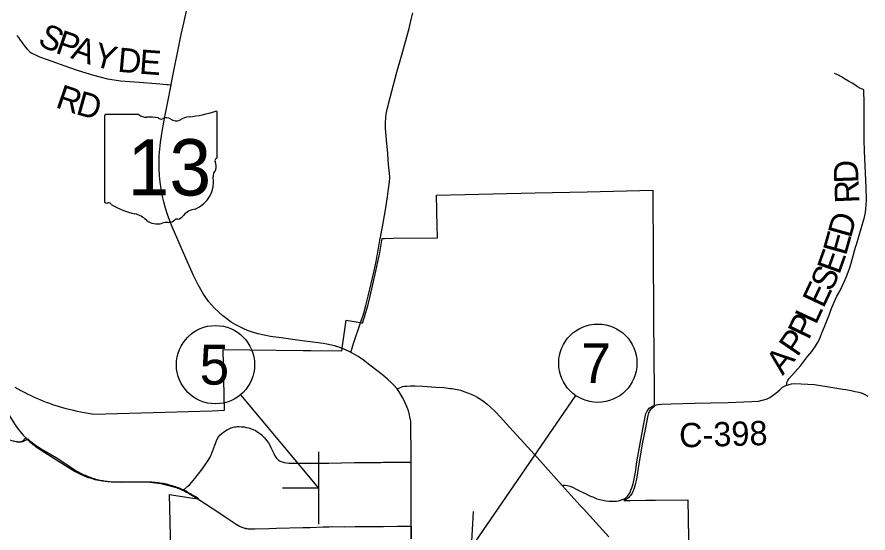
# Model space of a CAD drawing. Extents: x 40529 to 41139, y 15164 to 15584.
# Drawn here: x 40677.8 to 40737.7, y 15391.5 to 15427.7 of the extents above; entities that cross this region are included whole.
import ezdxf

# ---------------------------------------------------------------- set-up
doc = ezdxf.new("R2010")
doc.units = 0
for name, color, linetype in [('Default', 7, 'Continuous'), ('GM_X_Corporation', 7, 'Continuous'), ('GM_X_County_Road', 7, 'Continuous'), ('GM_X_County_Road_Text', 7, 'Continuous'), ('GM_X_State_Location', 7, 'Continuous'), ('GM_X_State_Route', 7, 'Continuous'), ('GM_X_State_Shield', 7, 'Continuous'), ('GM_X_Township_Road', 7, 'Continuous'), ('GM_X_Township_Road_Text', 7, 'Continuous'), ('SH_Data', 7, 'Continuous'), ('SH_Text', 7, 'Continuous')]:
    doc.layers.add(name, color=color, linetype=linetype)

msp = doc.modelspace()

# ---------------------------------------------------------------- linework, layer by layer
at = {"layer": 'Default'}
for p, q in [((40699.053, 15392.086), (40699.048, 15397.182)), ((40699.05, 15394.634), (40696.502, 15394.631)), ((40709.776, 15390.449), (40709.922, 15392.993))]:
    msp.add_line(p, q, dxfattribs=at)
at = {"layer": 'GM_X_Corporation'}
for points in [[(40677.684, 15401.723), (40677.895, 15401.602), (40678.108, 15401.484), (40678.322, 15401.37), (40678.539, 15401.259), (40678.758, 15401.152), (40678.978, 15401.049), (40679.2, 15400.949), (40679.423, 15400.853), (40679.649, 15400.761), (40679.875, 15400.673), (40680.103, 15400.589), (40680.333, 15400.508), (40680.564, 15400.431), (40680.796, 15400.359), (40681.029, 15400.29), (40681.264, 15400.225), (40681.499, 15400.164), (40681.795, 15400.093), (40682.051, 15400.036), (40682.309, 15399.982), (40682.568, 15399.933), (40682.827, 15399.888), (40683.228, 15399.826), (40691.537, 15400.05), (40692.408, 15400.114), (40692.321, 15404.358), (40697.953, 15404.3), (40698.487, 15404.294), (40700.671, 15404.272), (40700.718, 15404.618), (40700.963, 15406.416), (40701.954, 15406.248), (40702.106, 15406.205), (40702.331, 15406.898), (40702.484, 15407.435), (40702.654, 15408.1), (40703.064, 15409.868), (40703.202, 15410.515), (40703.286, 15410.945), (40703.304, 15411.046), (40703.501, 15412.166), (40703.666, 15412.167), (40704.274, 15412.173), (40707.388, 15412.201), (40707.352, 15413.986), (40707.348, 15414.156), (40707.327, 15415.212), (40714.26, 15415.365), (40717.919, 15415.446), (40722.534, 15415.548), (40722.561, 15410.772), (40722.582, 15407.158), (40722.605, 15403.275), (40722.612, 15402.043), (40722.62, 15400.712), (40722.62, 15400.589), (40722.621, 15400.532), (40722.625, 15400.336), (40722.491, 15400.261), (40722.422, 15400.208), (40722.365, 15400.146), (40722.318, 15400.074), (40722.278, 15399.996), (40722.232, 15399.913), (40722.197, 15399.827), (40722.169, 15399.72), (40721.978, 15398.741), (40721.785, 15397.737), (40721.564, 15396.449), (40721.481, 15395.898), (40721.46, 15395.712), (40721.374, 15395.255), (40721.291, 15394.893), (40721.206, 15394.624), (40721.138, 15394.448), (40721.074, 15394.283), (40721.012, 15394.189), (40720.96, 15394.116), (40720.897, 15394.041), (40720.832, 15393.968), (40720.756, 15393.899), (40720.673, 15393.85), (40720.586, 15393.809), (40720.477, 15393.768), (40720.481, 15393.764), (40720.859, 15393.768), (40720.935, 15393.769), (40722.015, 15393.78), (40722.721, 15393.787), (40724.997, 15393.81), (40725.116, 15385.709)], [(40688.711, 15387.419), (40688.541, 15394.18), (40690.184, 15393.933), (40690.608, 15393.869), (40690.516, 15393.928), (40690.392, 15394.007), (40690.257, 15394.088), (40690.101, 15394.177), (40690.027, 15394.216), (40689.85, 15394.309), (40689.712, 15394.421), (40689.61, 15394.469), (40689.506, 15394.515), (40689.401, 15394.559), (40689.296, 15394.602), (40689.19, 15394.642), (40689.083, 15394.681), (40688.976, 15394.718), (40688.868, 15394.753), (40688.76, 15394.786), (40688.651, 15394.817), (40688.541, 15394.847), (40688.431, 15394.874), (40688.32, 15394.9), (40688.209, 15394.923), (40688.098, 15394.945), (40687.986, 15394.964), (40687.874, 15394.982), (40687.762, 15394.998), (40687.649, 15395.011), (40687.536, 15395.023), (40687.514, 15395.025), (40687.423, 15395.033), (40687.31, 15395.041), (40687.196, 15395.047), (40687.083, 15395.051), (40686.862, 15395.053), (40684.948, 15395.037), (40684.849, 15395.037), (40684.749, 15395.038), (40684.65, 15395.042), (40684.551, 15395.047), (40684.452, 15395.054), (40684.353, 15395.063), (40684.254, 15395.073), (40684.156, 15395.085), (40684.058, 15395.099), (40683.96, 15395.115), (40683.862, 15395.132), (40683.764, 15395.151), (40683.667, 15395.172), (40683.571, 15395.194), (40683.474, 15395.218), (40683.379, 15395.244), (40683.283, 15395.271), (40683.188, 15395.3), (40683.094, 15395.331), (40683, 15395.363), (40682.907, 15395.397), (40682.814, 15395.433), (40682.722, 15395.47), (40682.631, 15395.509), (40682.54, 15395.549), (40682.45, 15395.591), (40682.361, 15395.635), (40682.273, 15395.68), (40682.185, 15395.727), (40682.098, 15395.775), (40682.012, 15395.824), (40681.927, 15395.876), (40681.828, 15395.938), (40680.569, 15396.75), (40679.526, 15397.354), (40679.268, 15397.526), (40679.019, 15397.711), (40678.78, 15397.909), (40678.602, 15398.077), (40678.448, 15397.986), (40678.412, 15397.965), (40678.361, 15397.939), (40678.308, 15397.917), (40678.278, 15397.905), (40678.223, 15397.888), (40678.192, 15397.88), (40678.161, 15397.874), (40678.104, 15397.865), (40678.046, 15397.861), (40677.988, 15397.86), (40677.931, 15397.864), (40677.873, 15397.872), (40677.842, 15397.878), (40677.786, 15397.892)]]:
    msp.add_lwpolyline(points, dxfattribs=at)
at = {"layer": 'GM_X_County_Road'}
for points in [[(40703.373, 15412.203), (40703.381, 15412.248), (40703.514, 15412.979), (40703.726, 15414.172), (40703.874, 15415.085), (40703.954, 15415.64), (40704.012, 15416.116), (40704.027, 15416.451), (40704.007, 15416.758), (40703.977, 15417.131), (40703.928, 15417.685), (40703.889, 15418.134), (40703.795, 15419.079), (40703.777, 15419.37), (40703.74, 15419.874), (40703.726, 15420.339), (40703.756, 15420.62), (40703.78, 15420.891), (40703.854, 15421.247), (40703.913, 15421.474), (40703.948, 15421.621), (40704.54, 15423.846), (40704.831, 15424.892), (40705.392, 15426.905), (40705.541, 15427.541), (40705.66, 15428)], [(40701.974, 15406.226), (40701.997, 15406.297), (40702.199, 15406.918), (40702.352, 15407.454), (40702.522, 15408.119), (40702.932, 15409.886), (40703.07, 15410.532), (40703.154, 15410.961), (40703.172, 15411.062), (40703.369, 15412.181), (40703.373, 15412.203)], [(40701.307, 15404.163), (40701.421, 15404.558), (40701.49, 15404.793), (40701.974, 15406.226)], [(40722.473, 15400.363), (40722.498, 15400.376), (40722.64, 15400.432), (40722.795, 15400.477), (40722.893, 15400.493), (40723.169, 15400.516), (40723.817, 15400.55), (40725.492, 15400.593), (40726.607, 15400.609), (40727.813, 15400.641), (40728.929, 15400.683), (40729.487, 15400.701), (40729.951, 15400.745), (40730.212, 15400.794), (40730.321, 15400.819), (40730.558, 15400.903), (40730.755, 15401.002), (40730.923, 15401.1), (40731.174, 15401.298), (40731.451, 15401.534), (40731.653, 15401.712), (40731.747, 15401.766), (40731.84, 15401.815), (40731.933, 15401.853)], [(40731.933, 15401.853), (40731.974, 15401.87), (40732.116, 15401.909), (40732.284, 15401.944), (40732.51, 15401.965), (40732.955, 15401.954), (40733.429, 15401.929), (40733.89, 15401.905), (40734.165, 15401.87), (40734.891, 15401.746), (40735.893, 15401.578), (40736.088, 15401.544), (40736.463, 15401.475), (40736.754, 15401.421), (40737.01, 15401.362), (40737.237, 15401.288), (40737.425, 15401.209), (40737.651, 15401.084)], [(40720.354, 15393.812), (40720.436, 15393.842), (40720.522, 15393.884), (40720.605, 15393.932), (40720.681, 15394.001), (40720.747, 15394.074), (40720.809, 15394.15), (40720.861, 15394.222), (40720.923, 15394.316), (40720.988, 15394.481), (40721.055, 15394.656), (40721.14, 15394.925), (40721.223, 15395.287), (40721.309, 15395.744), (40721.33, 15395.929), (40721.413, 15396.48), (40721.633, 15397.767), (40721.826, 15398.769), (40722.018, 15399.747), (40722.045, 15399.854), (40722.08, 15399.941), (40722.126, 15400.023), (40722.166, 15400.101), (40722.213, 15400.173), (40722.27, 15400.235), (40722.339, 15400.288), (40722.473, 15400.363)], [(40676.892, 15398.131), (40677.118, 15398.073), (40677.657, 15397.919), (40677.836, 15397.887), (40677.926, 15397.88), (40678.016, 15397.882), (40678.104, 15397.895), (40678.19, 15397.921), (40678.261, 15397.967), (40678.309, 15398.015), (40678.446, 15398.152)], [(40716.154, 15394.821), (40716.225, 15394.832), (40716.294, 15394.842), (40716.366, 15394.845), (40716.494, 15394.821), (40716.681, 15394.762), (40716.874, 15394.687), (40717.194, 15394.53), (40717.857, 15394.215), (40718.202, 15394.046), (40718.303, 15394.005)], [(40718.303, 15394.005), (40718.591, 15393.887), (40719.019, 15393.772), (40719.23, 15393.737), (40719.453, 15393.708), (40719.769, 15393.701), (40719.97, 15393.715), (40720.113, 15393.744), (40720.327, 15393.802), (40720.354, 15393.812)]]:
    msp.add_lwpolyline(points, dxfattribs=at)
at = {"layer": 'GM_X_State_Route'}
for p, q in [((40690.468, 15393.917), (40692.237, 15392.767)), ((40705.542, 15391.073), (40705.543, 15391.959))]:
    msp.add_line(p, q, dxfattribs=at)
for points in [[(40700.259, 15404.581), (40700.232, 15404.588), (40699.932, 15404.661), (40699.597, 15404.731), (40699.354, 15404.773), (40698.8, 15404.859), (40697.875, 15404.979), (40696.396, 15405.171), (40695.659, 15405.28), (40695.202, 15405.365), (40694.749, 15405.471), (40694.392, 15405.574), (40694.042, 15405.697), (40693.785, 15405.805), (40693.534, 15405.924), (40693.206, 15406.099), (40692.89, 15406.294), (40692.585, 15406.506), (40692.293, 15406.735), (40692.012, 15406.978), (40691.745, 15407.236), (40691.491, 15407.508), (40691.313, 15407.721), (40691.145, 15407.943), (40690.935, 15408.25), (40690.742, 15408.567), (40690.564, 15408.894), (40690.236, 15409.563), (40689.851, 15410.411), (40688.737, 15412.977), (40688.562, 15413.408), (40688.403, 15413.845), (40688.263, 15414.289), (40688.142, 15414.737), (40688.039, 15415.191), (40687.959, 15415.649), (40687.897, 15416.11), (40687.853, 15416.573), (40687.826, 15417.038), (40687.818, 15417.503), (40687.83, 15417.968), (40687.862, 15418.432), (40687.914, 15418.894), (40688.01, 15419.539), (40688.171, 15420.457), (40688.407, 15421.645), (40688.659, 15422.94), (40688.692, 15423.11), (40689.372, 15426.494), (40689.572, 15427.404), (40689.753, 15428.127)], [(40701.307, 15404.163), (40701.235, 15404.197), (40700.979, 15404.312), (40700.776, 15404.4), (40700.569, 15404.479), (40700.312, 15404.568), (40700.259, 15404.581)], [(40704.555, 15401.579), (40704.525, 15401.619), (40704.343, 15401.833), (40704.146, 15402.033), (40703.872, 15402.286), (40703.515, 15402.587), (40702.634, 15403.273), (40702.186, 15403.607), (40701.803, 15403.873), (40701.483, 15404.067), (40701.307, 15404.163)], [(40704.555, 15401.579), (40704.625, 15401.617), (40704.722, 15401.669), (40704.829, 15401.717), (40704.936, 15401.759), (40705.064, 15401.783), (40705.223, 15401.796), (40705.489, 15401.81), (40705.792, 15401.81), (40706.355, 15401.79), (40707.271, 15401.727), (40707.837, 15401.689), (40708.303, 15401.634), (40708.409, 15401.616), (40708.766, 15401.555), (40709.011, 15401.496), (40709.318, 15401.399), (40709.574, 15401.303), (40709.923, 15401.151), (40710.178, 15401.016), (40710.416, 15400.868), (40710.648, 15400.705), (40710.876, 15400.529), (40711.1, 15400.343), (40711.435, 15400.018), (40711.811, 15399.621), (40712.437, 15398.934), (40713.99, 15397.215), (40716.154, 15394.821), (40717.425, 15393.415), (40717.65, 15393.167), (40719.427, 15391.208)], [(40705.484, 15399.439), (40705.475, 15399.504), (40705.42, 15399.783), (40705.347, 15400.053), (40705.212, 15400.405), (40705.101, 15400.659), (40704.982, 15400.913), (40704.845, 15401.159), (40704.693, 15401.394), (40704.555, 15401.579)], [(40677.306, 15399.697), (40677.447, 15399.461), (40677.701, 15399.071), (40677.917, 15398.769), (40678.148, 15398.478), (40678.332, 15398.269), (40678.446, 15398.152)], [(40705.527, 15397.478), (40705.523, 15398.53), (40705.52, 15398.851), (40705.507, 15399.128), (40705.502, 15399.31), (40705.484, 15399.439)], [(40678.446, 15398.152), (40678.526, 15398.069), (40678.73, 15397.881), (40678.946, 15397.706), (40679.247, 15397.488), (40679.793, 15397.133), (40681.606, 15395.987), (40681.926, 15395.798), (40682.255, 15395.625), (40682.508, 15395.51), (40682.767, 15395.407), (40683.031, 15395.318), (40683.298, 15395.241), (40683.569, 15395.179), (40683.844, 15395.132), (40684.212, 15395.089), (40684.676, 15395.06), (40685.141, 15395.049), (40686.54, 15395.073), (40686.914, 15395.067), (40687.195, 15395.05), (40687.567, 15395.008), (40687.936, 15394.947), (40688.302, 15394.87), (40688.665, 15394.777), (40689.023, 15394.665), (40689.374, 15394.534), (40689.462, 15394.493)], [(40705.528, 15396.44), (40705.529, 15396.667), (40705.527, 15397.478)], [(40705.543, 15391.959), (40705.543, 15392.301), (40705.534, 15393.599), (40705.526, 15395.737), (40705.528, 15396.44)], [(40689.462, 15394.493), (40689.491, 15394.48), (40689.63, 15394.417), (40689.877, 15394.283), (40690.355, 15393.99), (40690.468, 15393.917)], [(40692.237, 15392.767), (40692.464, 15392.62), (40693.238, 15392.103), (40693.476, 15391.963), (40693.642, 15391.884), (40693.699, 15391.864)], [(40693.699, 15391.864), (40693.813, 15391.823), (40693.899, 15391.801), (40694.074, 15391.776), (40694.255, 15391.766), (40694.537, 15391.762), (40695.521, 15391.797), (40696.066, 15391.807), (40697.921, 15391.856), (40698.429, 15391.871), (40699.361, 15391.906), (40699.571, 15391.912)], [(40699.571, 15391.912), (40699.781, 15391.919), (40699.92, 15391.923), (40700.851, 15391.919), (40701.608, 15391.924), (40702.229, 15391.929), (40703.453, 15391.943), (40703.589, 15391.944), (40704.581, 15391.951), (40705.015, 15391.955), (40705.413, 15391.958), (40705.543, 15391.959)]]:
    msp.add_lwpolyline(points, dxfattribs=at)
at = {"layer": 'GM_X_State_Shield'}
for p, q in [((40683.987, 15420.758), (40683.987, 15414.755)), ((40686.381, 15420.862), (40684.065, 15420.862)), ((40691.897, 15417.87), (40691.897, 15421.01)), ((40691.896, 15417.871), (40691.897, 15417.87))]:
    msp.add_line(p, q, dxfattribs=at)
for centre, radius, start, end in [((40684.077, 15420.771), 0.0916, 98.1301, 188.1301), ((40686.933, 15421.559), 0.889, 231.61951, 271.11188), ((40687.227, 15417.491), 3.191, 80.48669, 94.98827), ((40687.952, 15420.802), 0.256, 219.79206, 297.10237), ((40688.328, 15420.108), 0.533, 54.46668, 119.14113), ((40690.149, 15419.028), 1.688, 97.34618, 120.76885), ((40689.079, 15429.047), 8.388, 275.84447, 288.90645), ((40691.809, 15421.024), 0.0881, 351.86209, 97.738), ((40689.016, 15421.06), 0.641, 233.85621, 294.82819), ((40691.876, 15417.639), 0.136, 107.94398, 210.33697), ((40691.009, 15417.242), 0.818, 340.03296, 23.64957), ((40691.803, 15417.858), 0.0942, 289.60381, 7.73413), ((40692.212, 15416.556), 0.595, 136.8065, 186.92959), ((40689.549, 15416.156), 2.098, 292.30889, 8.98584), ((40684.078, 15414.742), 0.0925, 171.95839, 258.30661), ((40684.092, 15415.356), 0.706, 267.33899, 280.60386), ((40684.237, 15414.408), 0.254, 29.74838, 93.27175), ((40687.448, 15419.802), 6.058, 240.41292, 257.1985), ((40690.434, 15413.069), 1.149, 94.40312, 142.57675), ((40685.642, 15412.058), 1.895, 47.18416, 75.83597), ((40687.692, 15414.379), 1.203, 230.70037, 286.29184), ((40688.475, 15413.929), 0.641, 268.77702, 315.54927), ((40689.055, 15413.348), 0.18, 65.75173, 132.64842), ((40688.978, 15414.173), 0.678, 282.87319, 323.27711), ((40688.387, 15412.303), 0.988, 85.69512, 111.20995)]:
    msp.add_arc(centre, radius, start, end, dxfattribs=at)
at = {"layer": 'GM_X_Township_Road'}
msp.add_line((40704.54, 15396.447), (40705.528, 15396.44), dxfattribs=at)
for points in [[(40677.817, 15426.421), (40677.93, 15426.263), (40678.058, 15426.081), (40678.162, 15425.948), (40678.266, 15425.805), (40678.394, 15425.622), (40678.542, 15425.45), (40678.729, 15425.267), (40678.833, 15425.199), (40678.911, 15425.15), (40679.075, 15425.068), (40679.418, 15424.927), (40679.943, 15424.739), (40681.523, 15424.178), (40682.135, 15423.956), (40682.665, 15423.782), (40683.198, 15423.619), (40683.647, 15423.5), (40684.19, 15423.38), (40684.647, 15423.298), (40685.107, 15423.237), (40685.756, 15423.174), (40686.406, 15423.126), (40687.612, 15423.047), (40688.353, 15422.976), (40688.446, 15422.965), (40688.659, 15422.94)], [(40737.368, 15422.592), (40737.312, 15422.614), (40737.263, 15422.634), (40737.198, 15422.663), (40737.085, 15422.721), (40736.926, 15422.814), (40736.725, 15422.946), (40736.543, 15423.062), (40736.274, 15423.209), (40735.999, 15423.374), (40735.801, 15423.503), (40735.575, 15423.632), (40735.422, 15423.698), (40735.299, 15423.736)], [(40731.933, 15401.853), (40731.944, 15401.959), (40731.954, 15402.057), (40732.023, 15402.185), (40732.09, 15402.301), (40732.911, 15403.207), (40733.389, 15403.873), (40733.7, 15404.233), (40733.969, 15404.593), (40734.11, 15404.827), (40734.233, 15405.096), (40734.391, 15405.456), (40734.613, 15406.026), (40734.941, 15406.853), (40735.041, 15407.125), (40735.124, 15407.35), (40735.266, 15407.694), (40735.469, 15408.109), (40735.69, 15408.514), (40735.969, 15409.107), (40736.137, 15409.501), (40736.329, 15409.97), (40736.474, 15410.418), (40736.784, 15411.543), (40736.841, 15411.74), (40737.173, 15412.871), (40737.242, 15413.088), (40737.296, 15413.26), (40737.38, 15413.566), (40737.473, 15413.977), (40737.51, 15414.251), (40737.531, 15414.526), (40737.537, 15414.895), (40737.526, 15415.73), (40737.486, 15416.753), (40737.413, 15418.323), (40737.387, 15419.063), (40737.385, 15419.616), (40737.388, 15420.075), (40737.385, 15420.438), (40737.38, 15421.637), (40737.368, 15422.592)], [(40689.491, 15394.48), (40689.621, 15394.59), (40689.829, 15394.766), (40689.97, 15394.891), (40690.099, 15395.027), (40690.339, 15395.313), (40690.845, 15395.961), (40691.066, 15396.258), (40691.273, 15396.57), (40691.415, 15396.808), (40691.452, 15396.89), (40691.723, 15397.634), (40691.846, 15397.94), (40691.94, 15398.157), (40692.083, 15398.339), (40692.221, 15398.467), (40692.339, 15398.556), (40692.477, 15398.655), (40692.568, 15398.71)], [(40692.568, 15398.71), (40692.591, 15398.724), (40692.739, 15398.798), (40692.892, 15398.862), (40693.03, 15398.911), (40693.148, 15398.931), (40693.242, 15398.941), (40693.331, 15398.946), (40693.424, 15398.946), (40693.607, 15398.941), (40693.789, 15398.926), (40693.947, 15398.897), (40694.12, 15398.852), (40694.308, 15398.793), (40694.584, 15398.675), (40694.83, 15398.518), (40694.976, 15398.408), (40695.029, 15398.36)], [(40695.029, 15398.36), (40695.044, 15398.346), (40695.229, 15398.156), (40695.4, 15397.949), (40695.504, 15397.8), (40695.598, 15397.643), (40695.682, 15397.48), (40695.871, 15397.056), (40695.96, 15396.889), (40696.013, 15396.81), (40696.073, 15396.735), (40696.14, 15396.666), (40696.212, 15396.603), (40696.29, 15396.547), (40696.374, 15396.499), (40696.468, 15396.464), (40696.537, 15396.44), (40696.607, 15396.424), (40696.778, 15396.398), (40696.945, 15396.389), (40697.682, 15396.39), (40699.745, 15396.391)], [(40699.745, 15396.391), (40700.637, 15396.405), (40701.562, 15396.42)], [(40701.562, 15396.42), (40703.393, 15396.439), (40703.545, 15396.44)], [(40703.545, 15396.44), (40704.455, 15396.448), (40704.54, 15396.447)]]:
    msp.add_lwpolyline(points, dxfattribs=at)
at = {"layer": 'SH_Data'}
for p, q in [((40699.05, 15394.634), (40693.551, 15401.189)), ((40709.776, 15390.449), (40717.103, 15401.133))]:
    msp.add_line(p, q, dxfattribs=at)
msp.add_lwpolyline([(40677.701, 15399.071), (40677.917, 15398.769), (40678.148, 15398.478), (40678.24, 15398.374), (40678.332, 15398.269), (40678.446, 15398.152), (40678.526, 15398.069), (40678.73, 15397.881), (40678.946, 15397.706), (40679.247, 15397.488), (40679.793, 15397.133), (40681.606, 15395.987), (40681.926, 15395.798), (40682.255, 15395.625), (40682.508, 15395.51), (40682.767, 15395.407), (40683.031, 15395.318), (40683.298, 15395.241), (40683.572, 15395.179), (40683.844, 15395.132), (40684.212, 15395.089), (40684.676, 15395.06), (40685.141, 15395.049), (40686.54, 15395.073), (40686.914, 15395.067), (40687.195, 15395.05), (40687.567, 15395.008), (40687.936, 15394.947), (40688.302, 15394.87), (40688.665, 15394.777), (40689.023, 15394.665), (40689.374, 15394.534), (40689.493, 15394.479), (40689.63, 15394.417), (40689.753, 15394.35), (40689.877, 15394.283), (40690.355, 15393.99), (40690.468, 15393.917), (40692.237, 15392.767), (40692.464, 15392.62), (40693.238, 15392.103), (40693.357, 15392.033), (40693.476, 15391.963), (40693.699, 15391.864), (40693.856, 15391.812), (40694.164, 15391.771), (40694.255, 15391.766), (40695.521, 15391.797), (40696.066, 15391.807), (40697.921, 15391.856), (40698.429, 15391.871), (40699.361, 15391.906), (40699.571, 15391.912), (40699.781, 15391.919), (40699.92, 15391.923), (40700.851, 15391.919), (40701.608, 15391.924), (40702.229, 15391.929), (40703.453, 15391.943), (40704.581, 15391.951), (40705.015, 15391.955), (40705.413, 15391.958), (40705.543, 15391.959), (40705.542, 15391.073)], dxfattribs=at)
at = {"layer": 'SH_Text'}
for centre in [(40691.783, 15403.296), (40718.659, 15403.401)]:
    msp.add_circle(centre, 2.75, dxfattribs=at)

# ---------------------------------------------------------------- texts
at = {"layer": 'GM_X_County_Road_Text'}
msp.add_text('C-398', height=1.7063, rotation=1.6616, dxfattribs=at).set_placement((40724.398, 15397.478))
at = {"layer": 'GM_X_State_Location'}
for s, p in [('s', (40687.853, 15417.357)), ('r', (40687.852, 15417.357))]:
    msp.add_text(s, height=0.00568, dxfattribs=at).set_placement(p)
msp.add_text('13', height=0.00568, rotation=0.00001, dxfattribs=at).set_placement((40686.422, 15416.944))
at = {"layer": 'GM_X_State_Shield'}
msp.add_text('13', height=3.9551, dxfattribs=at).set_placement((40685.596, 15415.178))
at = {"layer": 'GM_X_Township_Road_Text'}
for s, rotation, p in [('S', 333.86844, (40679.205, 15425.812)), ('P', 341.11821, (40680.456, 15425.215)), ('A', 340.87619, (40681.544, 15424.843)), ('Y', 345.36374, (40683.102, 15424.308)), ('D', 354.81734, (40684.858, 15423.876)), ('E', 355.72842, (40686.382, 15423.738)), ('R', 341.09603, (40680.466, 15421.393)), ('D', 344.49226, (40681.895, 15420.907)), ('D', 92.08052, (40736.989, 15416.059)), ('R', 92.37312, (40737.047, 15414.661)), ('D', 74.37683, (40736.446, 15412.127)), ('E', 74.42738, (40736.104, 15410.898)), ('E', 70.24857, (40735.631, 15409.567)), ('S', 64.55483, (40735.065, 15408.357)), ('E', 64.83423, (40734.523, 15407.204)), ('P', 64.26919, (40733.479, 15404.976)), ('L', 65.42966, (40733.995, 15406.047)), ('P', 55.74078, (40732.692, 15403.785)), ('A', 51.07223, (40731.658, 15402.495))]:
    msp.add_text(s, height=1.706, rotation=rotation, dxfattribs=at).set_placement(p)
at = {"layer": 'SH_Text'}
for s, p in [('5', (40690.664, 15401.896)), ('7', (40717.495, 15402.001))]:
    msp.add_text(s, height=2.8, dxfattribs=at).set_placement(p)

doc.saveas('drawing.dxf')
